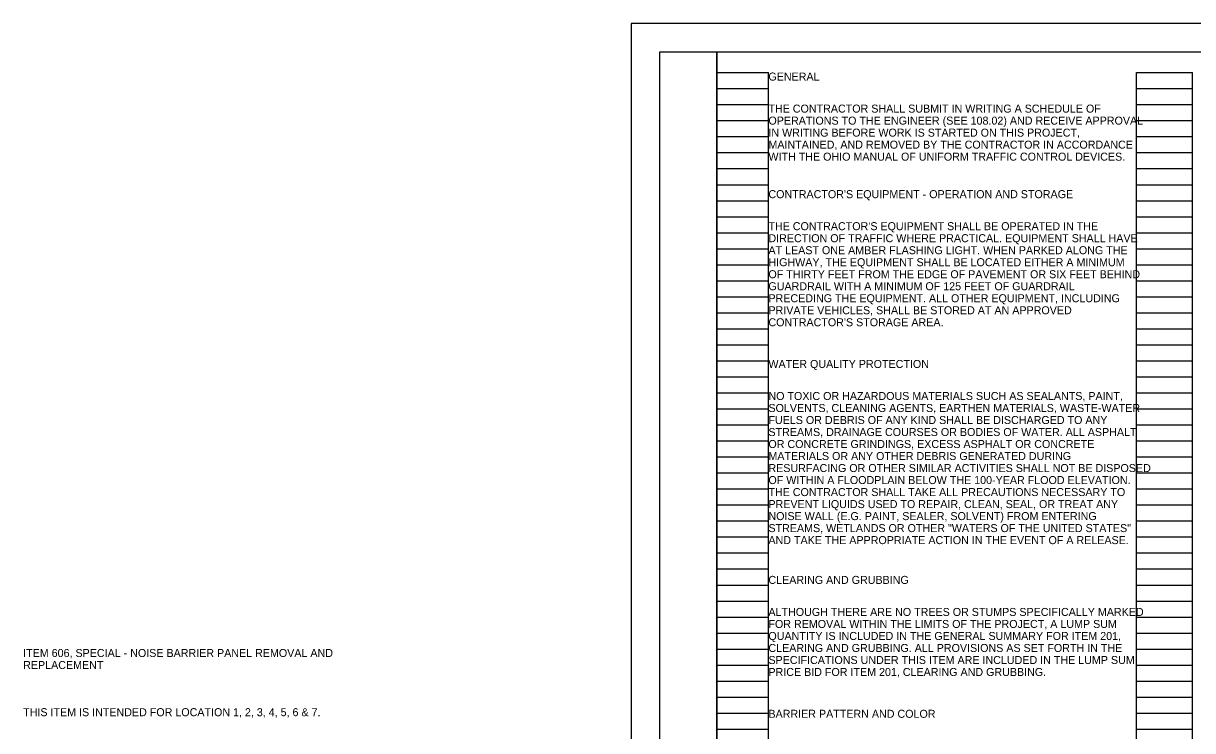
# Model space of a CAD drawing. Extents: x -10.6 to 34, y -3 to 22.
# Drawn here: x -10.63 to 9.82, y 9.63 to 22 of the extents above; entities that cross this region are included whole.
import ezdxf

# ---------------------------------------------------------------- set-up
doc = ezdxf.new("R2010")
doc.units = 0
for name, color, linetype in [('SH_Border', 7, 'Continuous'), ('SH_Cut_Line', 7, 'Continuous'), ('SH_Data', 7, 'Continuous'), ('SH_Text', 7, 'Continuous')]:
    doc.layers.add(name, color=color, linetype=linetype)

msp = doc.modelspace()

# ---------------------------------------------------------------- linework, layer by layer
at = {"layer": 'SH_Border'}
for points in [[(0.5, 21.5), (1.5, 21.5), (1.5, 0.5), (0.5, 0.5)], [(1.5, 21.5), (33.5, 21.5), (33.5, 0.5), (1.5, 0.5)]]:
    msp.add_lwpolyline(points, close=True, dxfattribs=at)
at = {"layer": 'SH_Cut_Line'}
msp.add_lwpolyline([(0, 0), (34, 0), (34, 22), (0, 22)], close=True, dxfattribs=at)
at = {"layer": 'SH_Data'}
for p, q in [((1.5, 0.98), (1.5, 21.14)), ((1.5, 21.14), (2.4, 21.14)), ((2.4, 0.98), (2.4, 21.14)), ((8.84, 0.98), (8.84, 21.14)), ((8.84, 21.14), (9.82, 21.14)), ((9.82, 0.98), (9.82, 21.14)), ((1.5, 20.86), (2.4, 20.86)), ((8.84, 20.86), (9.82, 20.86)), ((1.5, 20.58), (2.4, 20.58)), ((8.84, 20.58), (9.82, 20.58)), ((1.5, 20.3), (2.4, 20.3)), ((8.84, 20.3), (9.82, 20.3)), ((1.5, 20.02), (2.4, 20.02)), ((8.84, 20.02), (9.82, 20.02)), ((1.5, 19.74), (2.4, 19.74)), ((8.84, 19.74), (9.82, 19.74)), ((1.5, 19.46), (2.4, 19.46)), ((8.84, 19.46), (9.82, 19.46)), ((1.5, 19.18), (2.4, 19.18)), ((8.84, 19.18), (9.82, 19.18)), ((1.5, 18.9), (2.4, 18.9)), ((8.84, 18.9), (9.82, 18.9)), ((1.5, 18.62), (2.4, 18.62)), ((8.84, 18.62), (9.82, 18.62)), ((1.5, 18.34), (2.4, 18.34)), ((8.84, 18.34), (9.82, 18.34)), ((1.5, 18.06), (2.4, 18.06)), ((8.84, 18.06), (9.82, 18.06)), ((1.5, 17.78), (2.4, 17.78)), ((8.84, 17.78), (9.82, 17.78)), ((1.5, 17.5), (2.4, 17.5)), ((8.84, 17.5), (9.82, 17.5)), ((1.5, 17.22), (2.4, 17.22)), ((8.84, 17.22), (9.82, 17.22)), ((1.5, 16.94), (2.4, 16.94)), ((8.84, 16.94), (9.82, 16.94)), ((1.5, 16.66), (2.4, 16.66)), ((8.84, 16.66), (9.82, 16.66)), ((1.5, 16.38), (2.4, 16.38)), ((8.84, 16.38), (9.82, 16.38)), ((1.5, 16.1), (2.4, 16.1)), ((8.84, 16.1), (9.82, 16.1)), ((1.5, 15.82), (2.4, 15.82)), ((8.84, 15.82), (9.82, 15.82)), ((1.5, 15.54), (2.4, 15.54)), ((8.84, 15.54), (9.82, 15.54)), ((1.5, 15.26), (2.4, 15.26)), ((8.84, 15.26), (9.82, 15.26)), ((1.5, 14.98), (2.4, 14.98)), ((8.84, 14.98), (9.82, 14.98)), ((1.5, 14.7), (2.4, 14.7)), ((8.84, 14.7), (9.82, 14.7)), ((1.5, 14.42), (2.4, 14.42)), ((8.84, 14.42), (9.82, 14.42)), ((1.5, 14.14), (2.4, 14.14)), ((8.84, 14.14), (9.82, 14.14)), ((1.5, 13.86), (2.4, 13.86)), ((8.84, 13.86), (9.82, 13.86)), ((1.5, 13.58), (2.4, 13.58)), ((8.84, 13.58), (9.82, 13.58)), ((1.5, 13.3), (2.4, 13.3)), ((8.84, 13.3), (9.82, 13.3)), ((1.5, 13.02), (2.4, 13.02)), ((8.84, 13.02), (9.82, 13.02)), ((1.5, 12.74), (2.4, 12.74)), ((8.84, 12.74), (9.82, 12.74)), ((1.5, 12.46), (2.4, 12.46)), ((8.84, 12.46), (9.82, 12.46)), ((1.5, 12.18), (2.4, 12.18)), ((8.84, 12.18), (9.82, 12.18)), ((1.5, 11.9), (2.4, 11.9)), ((8.84, 11.9), (9.82, 11.9)), ((1.5, 11.62), (2.4, 11.62)), ((8.84, 11.62), (9.82, 11.62)), ((1.5, 11.34), (2.4, 11.34)), ((8.84, 11.34), (9.82, 11.34)), ((1.5, 11.06), (2.4, 11.06)), ((8.84, 11.06), (9.82, 11.06)), ((1.5, 10.78), (2.4, 10.78)), ((8.84, 10.78), (9.82, 10.78)), ((1.5, 10.5), (2.4, 10.5)), ((8.84, 10.5), (9.82, 10.5)), ((1.5, 10.22), (2.4, 10.22)), ((8.84, 10.22), (9.82, 10.22)), ((1.5, 9.94), (2.4, 9.94)), ((8.84, 9.94), (9.82, 9.94)), ((1.5, 9.66), (2.4, 9.66)), ((8.84, 9.66), (9.82, 9.66))]:
    msp.add_line(p, q, dxfattribs=at)

# ---------------------------------------------------------------- texts
at = {"layer": 'SH_Text'}
for s, p in [('GENERAL', (2.4, 21)), ('THE CONTRACTOR SHALL SUBMIT IN WRITING A SCHEDULE OF ', (2.4, 20.44)), ('OPERATIONS TO THE ENGINEER (SEE 108.02) AND RECEIVE APPROVAL ', (2.4, 20.23)), ('IN WRITING BEFORE WORK IS STARTED ON THIS PROJECT, ', (2.4, 20.02)), ('MAINTAINED, AND REMOVED BY THE CONTRACTOR IN ACCORDANCE ', (2.4, 19.81)), ('WITH THE OHIO MANUAL OF UNIFORM TRAFFIC CONTROL DEVICES.', (2.4, 19.6)), ("CONTRACTOR'S EQUIPMENT - OPERATION AND STORAGE", (2.4, 18.944)), ("THE CONTRACTOR'S EQUIPMENT SHALL BE OPERATED IN THE ", (2.4, 18.384)), ('DIRECTION OF TRAFFIC WHERE PRACTICAL. EQUIPMENT SHALL HAVE ', (2.4, 18.174)), ('AT LEAST ONE AMBER FLASHING LIGHT. WHEN PARKED ALONG THE ', (2.4, 17.964)), ('HIGHWAY, THE EQUIPMENT SHALL BE LOCATED EITHER A MINIMUM ', (2.4, 17.754)), ('OF THIRTY FEET FROM THE EDGE OF PAVEMENT OR SIX FEET BEHIND ', (2.4, 17.544)), ('GUARDRAIL WITH A MINIMUM OF 125 FEET OF GUARDRAIL ', (2.4, 17.334)), ('PRECEDING THE EQUIPMENT. ALL OTHER EQUIPMENT, INCLUDING ', (2.4, 17.124)), ('PRIVATE VEHICLES, SHALL BE STORED AT AN APPROVED ', (2.4, 16.914)), ("CONTRACTOR'S STORAGE AREA.", (2.4, 16.704)), ('WATER QUALITY PROTECTION', (2.4, 15.975)), ('NO TOXIC OR HAZARDOUS MATERIALS SUCH AS SEALANTS, PAINT, ', (2.4, 15.415)), ('SOLVENTS, CLEANING AGENTS, EARTHEN MATERIALS, WASTE-WATER ', (2.4, 15.205)), ('FUELS OR DEBRIS OF ANY KIND SHALL BE DISCHARGED TO ANY ', (2.4, 14.995)), ('STREAMS, DRAINAGE COURSES OR BODIES OF WATER. ALL ASPHALT ', (2.4, 14.785)), ('OR CONCRETE GRINDINGS, EXCESS ASPHALT OR CONCRETE ', (2.4, 14.575)), ('MATERIALS OR ANY OTHER DEBRIS GENERATED DURING ', (2.4, 14.365)), ('RESURFACING OR OTHER SIMILAR ACTIVITIES SHALL NOT BE DISPOSED ', (2.4, 14.155)), ('OF WITHIN A FLOODPLAIN BELOW THE 100-YEAR FLOOD ELEVATION. ', (2.4, 13.945)), ('THE CONTRACTOR SHALL TAKE ALL PRECAUTIONS NECESSARY TO ', (2.4, 13.735)), ('PREVENT LIQUIDS USED TO REPAIR, CLEAN, SEAL, OR TREAT ANY ', (2.4, 13.525)), ('NOISE WALL (E.G. PAINT, SEALER, SOLVENT) FROM ENTERING ', (2.4, 13.315)), ('STREAMS, WETLANDS OR OTHER "WATERS OF THE UNITED STATES" ', (2.4, 13.105)), ('AND TAKE THE APPROPRIATE ACTION IN THE EVENT OF A RELEASE.', (2.4, 12.895)), ('CLEARING AND GRUBBING', (2.4, 12.199)), ('ALTHOUGH THERE ARE NO TREES OR STUMPS SPECIFICALLY MARKED ', (2.4, 11.639)), ('FOR REMOVAL WITHIN THE LIMITS OF THE PROJECT, A LUMP SUM ', (2.4, 11.429)), ('QUANTITY IS INCLUDED IN THE GENERAL SUMMARY FOR ITEM 201, ', (2.4, 11.219)), ('ITEM 606, SPECIAL - NOISE BARRIER PANEL REMOVAL AND ', (-10.637, 10.921)), ('CLEARING AND GRUBBING. ALL PROVISIONS AS SET FORTH IN THE ', (2.4, 11.009)), ('REPLACEMENT', (-10.637, 10.711)), ('SPECIFICATIONS UNDER THIS ITEM ARE INCLUDED IN THE LUMP SUM ', (2.4, 10.799)), ('PRICE BID FOR ITEM 201, CLEARING AND GRUBBING.', (2.4, 10.589)), ('THIS ITEM IS INTENDED FOR LOCATION 1, 2, 3, 4, 5, 6 & 7. ', (-10.637, 9.886)), ('BARRIER PATTERN AND COLOR', (2.4, 9.858))]:
    msp.add_text(s, height=0.14, dxfattribs=at).set_placement(p)

doc.saveas('drawing.dxf')
